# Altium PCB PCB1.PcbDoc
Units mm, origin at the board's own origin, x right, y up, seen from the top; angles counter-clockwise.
Board outline 17.78 x 17.78 mm, 2 copper layers (Top Layer, Bottom Layer); 15 components, 7 nets, 44 pads, 7 vias.
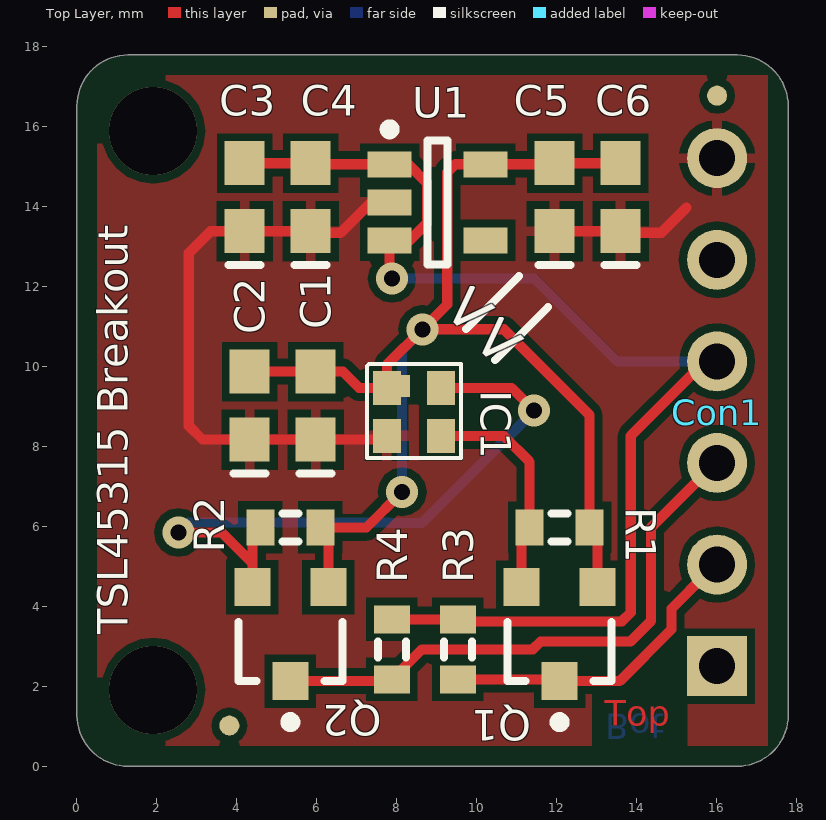
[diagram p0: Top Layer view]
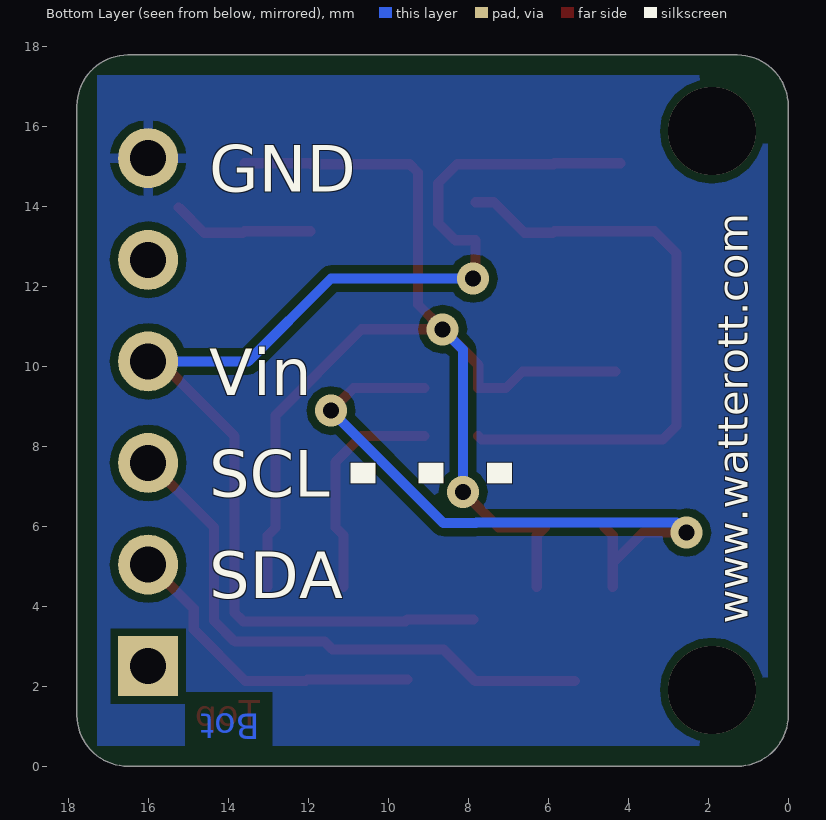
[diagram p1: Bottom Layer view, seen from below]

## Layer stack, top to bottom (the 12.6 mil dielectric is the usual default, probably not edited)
Top Layer: signal copper 0.0356
Dielectric: dielectric 0.32, FR-4, Dk 4.8
Bottom Layer: signal copper 0.0356

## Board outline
0,1.27 0,16.51 cw(c1.27,16.51) 1.27,17.78 16.51,17.78 cw(c16.51,16.51) 17.78,16.51 17.78,1.27 cw(c16.51,1.27) 16.51,0 1.27,0 cw(c1.27,1.27)

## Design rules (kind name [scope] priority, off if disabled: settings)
Clearance [All] p1: gap=0.2
PolygonConnect [All] p1: connectstyle=Relief reliefconductorwidth=0.254 reliefentries=4 polygonreliefangle="90 Angle"
RoomDefinition Sheet1 [InComponentClass('Sheet1')] p1: confinementstyle=ConfineIn formatcopy=TRUE lockcomponents=FALSE outline 0,0 17.78,0 17.78,17.78 0,17.78
RoutingVias [All] p1: holewidth=0.4 width=0.8 viastyle="Through Hole" minholewidth=0.3 minwidth=0.8 maxholewidth=1 maxwidth=2
SilkscreenOverComponentPads [All] p1: minsilkscreentomaskgap=0.254
SolderMaskExpansion [All] p1: expansion=0.102
Width [All] p1: maxlimit=0.254 minlimit=0.254 preferedwidth=0.254
27 further rules are at their usual default settings.

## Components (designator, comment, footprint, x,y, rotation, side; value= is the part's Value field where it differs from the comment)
C1 "2,2µ" 0603 5.969,9.017 r90 top
C2 "100nF" 0603 4.318,9.017 r90 top
C3 "2,2µ" 0603 4.191,14.224 r90 top
C4 "100nF" 0603 5.842,14.224 r90 top
C5 "100nF" 0603 11.938,14.224 r90 top
C6 "2,2µ" 0603 13.589,14.224 r90 top
Con1 "Header 6H" HDR1X6 16.002,2.5 r90 top
IC1 "TSL45315" TSL4531 7.747,8.255 r0 top
Q1 "BSS138" SOT23 12.065,3.302 r180 top
Q2 "BSS138" SOT23 5.334,3.302 r180 top
R1 "4k7" J1-0603 12.065,5.969 r0 top
R2 "4k7" J1-0603 5.334,5.969 r0 top
R3 "4k7" J1-0603 9.525,2.921 r90 top
R4 "4k7" J1-0603 7.874,2.921 r90 top
U1 "TS5205CX525" MF05A_N 9.017,14.097 r0 top

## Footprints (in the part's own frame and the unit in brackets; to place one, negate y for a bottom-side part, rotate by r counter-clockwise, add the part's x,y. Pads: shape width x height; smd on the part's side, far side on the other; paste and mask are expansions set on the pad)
0603 [mm] "Chip Capacitor; Body 1.6 x 0.8 mm (LxW typ)"
  rect 1.1x1 smd: 1(-0.85,0) 2(0.85,0)
  silkscreen extent -1.7,-0.4 -1.7,0.4
HDR1X6 [mm] "Connector; Header; 6 Position"
  rect 1.5x1.5 hole 0.9: 1(0,0)
  round 1.5 hole 0.9: 2(2.54,0) 3(5.08,0) 4(7.62,0) 5(10.16,0) 6(12.7,0)
J1-0603 [mm] "Chip Resistor, Body 1.6x0.8mm, IPC High Density"
  rect 0.7x0.9 smd: 1(-0.75,0) 2(0.75,0)
  silkscreen extent -0.2,-0.35 0.2,0.35, body extent -0.85,-0.48 0.85,0.48, height 0.9
MF05A_N [mm] "SOT23, 5-Leads, Body 2.9x1.6mm, Pitch 0.95mm, Lead Span 2.8mm, IPC Medium Density"
  rect 1.1x0.65 smd: 1(-1.2,0.95) 2(-1.2,0) 3(-1.2,-0.95) 4(1.2,-0.95) 5(1.2,0.95)
  silkscreen extent -1.32,-1.55 0.25,1.95, body extent -0.9,-1.55 0.9,1.55, height 1.22
SOT23 [mm] "SOT-23; 3 Leads; Body 3.1 x 2.5 mm, inc. leads (LxW max), Alternate Lead Configuration"
  rect 0.9x0.95 smd: 1(0,1.175) 2(0.95,-1.175) 3(-0.95,-1.175)
  silkscreen extent -1.3,-0.3 1.3,2.32
TSL4531 [mm]
  rect 0.7x0.85 smd: 1(0,1.2) 2(0,0) 3(1.35,0) 4(1.35,1.2)
  rect 0.25x0.55 smd: 1(0.45,1.25)
  silkscreen extent -0.5,-0.55 1.85,1.8

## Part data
C1 C2 C3 C4 C5 C6: library part C0603, "Ceramic Chip Capacitor - Standard"
Con1: "Header, 6-Pin, Right Angle"
Q1 Q2: "N-Channel Enhancement Mode Vertical DMOS FET"
R1 R2 R3 R4: library part Res3, "Resistor"
U1: library part LP2985AIM5-2.5, "Micropower 150 mA Low-Noise Ultra Low-Dropout Regulator in  SOT-23 and micro SMD Packages"

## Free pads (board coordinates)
  round 0.5 smd mask+0.2: 0(3.81,1.016) 1(16.002,16.764)

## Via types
v1: diameter 0.8, hole 0.4, Top Layer to Bottom Layer, tented both sides, 5 vias
v2: diameter 2.2, hole 2.2, Top Layer to Bottom Layer, 2 vias

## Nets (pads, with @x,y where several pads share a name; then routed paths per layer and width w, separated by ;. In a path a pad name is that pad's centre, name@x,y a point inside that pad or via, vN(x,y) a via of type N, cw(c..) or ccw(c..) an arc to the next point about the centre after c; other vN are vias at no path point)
GND: C1.1 C2.1 C3.1 C4.1 C5.1 C6.1 Con1.6 IC1.2 U1.2 | length 18.6
  Top Layer w0.254: IC1.2 7.659,8.167 C1.1 C2.1 3.136,8.167 2.794,8.509 2.794,12.827 3.341,13.374 C3.1 C4.1 5.881,13.335 6.591,13.335 7.353,14.097 U1.2 ; C5.1 C6.1 13.628,13.335 14.605,13.335 15.24,13.97
NetCon1_2: Con1.2 Q1.1 R3.1 | length 8
  Top Layer w0.254: R3.1 12.021,2.171 Q1.1 13.566,2.127 14.862,3.423 14.862,3.94 15.748,4.826 Con1.2@16.002,4.572
NetCon1_3: Con1.3 Q2.1 R4.1 | length 14.1
  Top Layer w0.254: Q2.1 7.83,2.127 R4.1 8.624,2.921 11.395,2.921 11.587,3.113 13.833,3.113 14.354,3.634 14.354,5.972 15.494,7.112 Con1.3@16.002,7.112
NetIC1_3: IC1.3 Q1.2 R1.1 | length 5.7
  Top Layer w0.254: IC1.3 10.668,8.255 11.315,7.608 R1.1 11.115,5.769 Q1.2
NetIC1_4: IC1.4 Q2.2 R2.1 | length 16.5
  Top Layer w0.254: v1(2.54,5.842) 3.622,5.842 4.384,5.08 ; Q2.2 4.384,5.08 ; R2.1 4.384,5.769 4.384,5.08 ; IC1.4 10.865,9.455 v1(11.43,8.89)
  Bottom Layer w0.254: v1(2.54,5.842) 2.794,6.096 7.785,6.096 7.805,6.077 8.617,6.077 v1(11.43,8.89)
VDD: C1.2 C2.2 C5.2 C6.2 IC1.1 Q1.3 Q2.3 R1.2 R2.2 U1.5 | length 31.8
  Top Layer w0.254: C2.2 C1.2 6.643,9.867 7.055,9.455 7.747,9.455 7.747,10.033 v1(8.636,10.922) ; Q2.3 6.284,5.769 R2.2 7.239,5.969 v1(8.128,6.858) ; Q1.3 13.015,5.769 R1.2 12.815,8.775 10.668,10.922 v1(8.636,10.922) ; C6.2 C5.2 11.911,15.047 U1.5 9.459,15.047 9.256,14.844 9.256,11.542 v1(8.636,10.922)
  Bottom Layer w0.254: v1(8.128,6.858) 8.128,10.414 v1(8.636,10.922)
VIN: C3.2 C4.2 Con1.4 R3.2 R4.2 U1.1 U1.3 | length 30.6
  Top Layer w0.254: C3.2 C4.2 5.869,15.047 U1.1 8.281,15.047 8.748,14.58 8.748,13.574 8.321,13.147 U1.3 7.817,12.249 v1(7.874,12.192) ; R4.2 R3.2 9.575,3.621 13.623,3.621 13.846,3.844 13.846,8.258 15.621,10.033 Con1.4@16.002,9.652
  Bottom Layer w0.254: v1(7.874,12.192) 11.43,12.192 13.502,10.12 15.497,10.12 Con1.4@16.002,9.652
pads on no net: Con1.1 Con1.5 U1.4
copper on no net:
  other v2: 1.905,1.905 1.905,15.875

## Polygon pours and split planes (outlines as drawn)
GND on Top Layer "GND_Top" (solid, remove dead copper, pour order 2): 0.508,0.508 17.272,0.508 17.272,17.272 0.508,17.272
GND on Bottom Layer "GND_Bot" (solid, remove dead copper, pour order 4): 0.508,0.508 17.272,0.508 17.272,17.272 0.508,17.272

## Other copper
Top Layer:
  text "Top" at 13.2,0.8 h1.1
Bottom Layer:
  text "Bot" at 13.208,1.524 h1.1 r180

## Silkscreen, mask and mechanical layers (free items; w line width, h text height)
Top Overlay:
  lines w0.2: 9.725,10.925 11.05,12.25 ; 10.45,10.15 11.775,11.475
  text "<" at 9.975,10.3 h2 r45
  text "<" at 10.7,9.525 h2 r45
  text "TSL45315 Breakout" at 1.524,3.302 h1.3 r90
Bottom Overlay:
  text "GND" at 14.478,13.97 h2
  text "Vin" at 14.478,8.89 h2
  text "SCL" at 14.478,6.35 h2
  text "⋮" at 5.842,4.826 h8 r270
  text "SDA" at 14.478,3.81 h2
  text "www.watterott.com" at 0.762,3.556 h1.3 r270
Mechanical 1:
  the board outline again, w0.01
